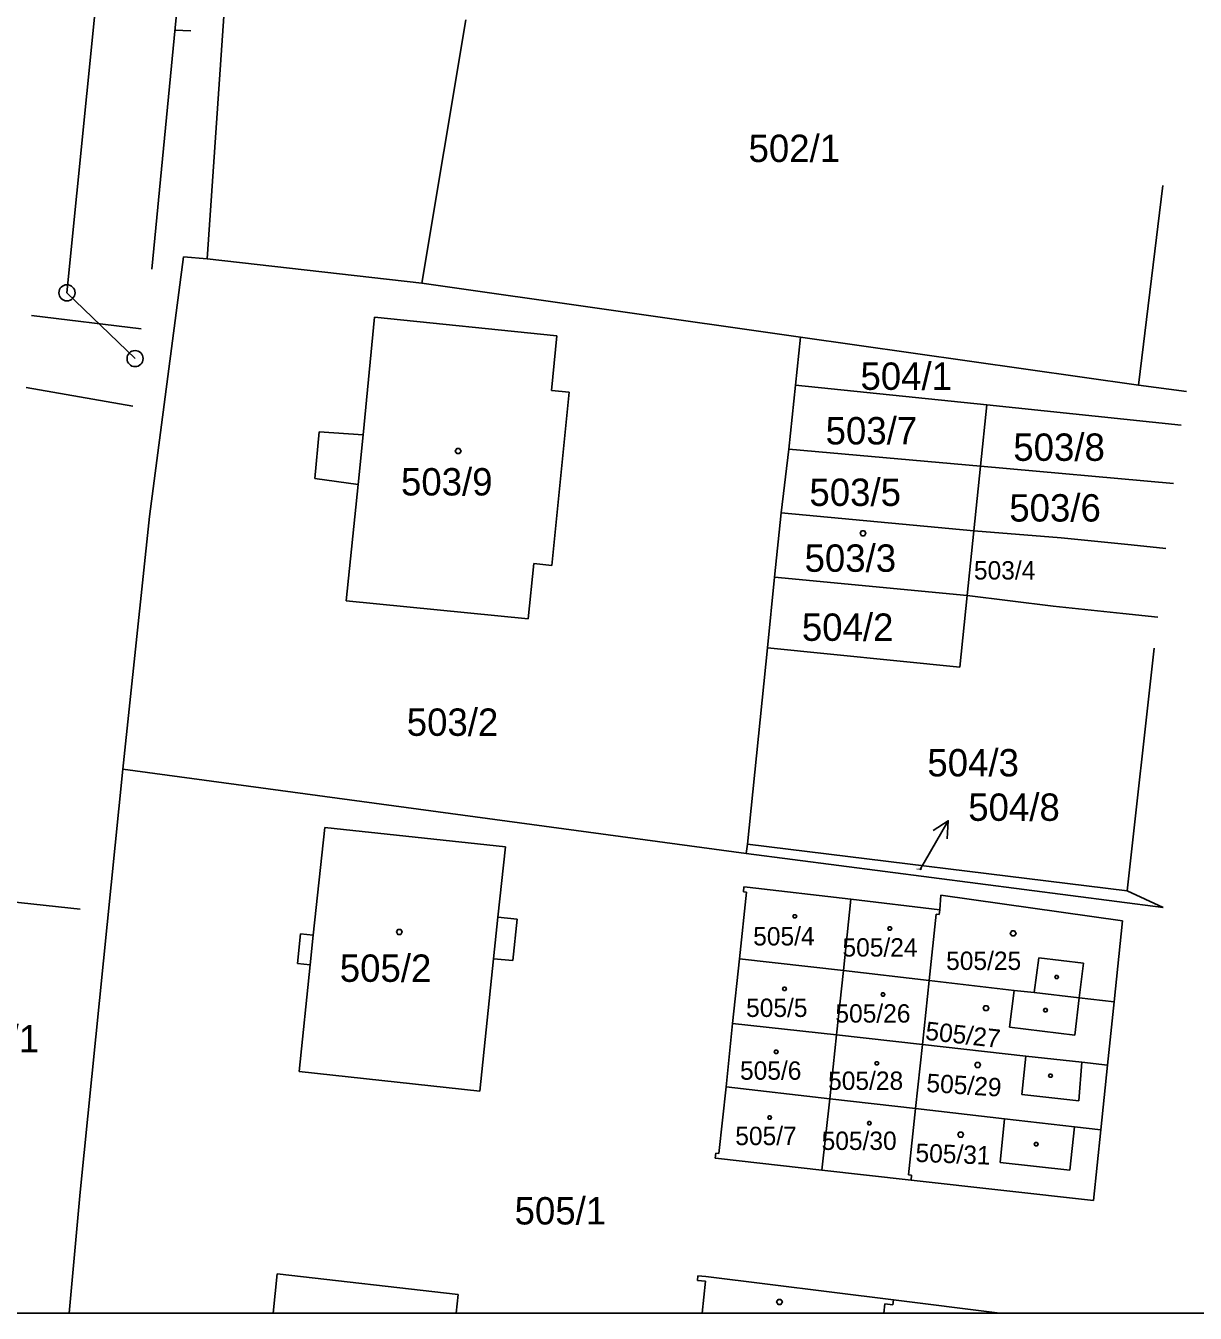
# Model space of a CAD drawing. Extents: x -639621 to -639329, y -1192893 to -1192488.
# Drawn here: x -639505.7 to -639433, y -1192893.3 to -1192813.4 of the extents above; entities that cross this region are included whole.
import ezdxf

# ---------------------------------------------------------------- set-up
doc = ezdxf.new("R2010")
doc.units = 0
for name, color, linetype in [('Vrstva 1', 7, 'Continuous'), ('Vrstva 19', 7, 'Continuous'), ('Vrstva 2', 7, 'Continuous'), ('Vrstva 24', 7, 'Continuous'), ('Vrstva 25', 7, 'Continuous'), ('Vrstva 4', 7, 'Continuous'), ('Vrstva 5', 7, 'Continuous'), ('Vrstva 61', 7, 'Continuous'), ('Vrstva 7', 7, 'Continuous')]:
    doc.layers.add(name, color=color, linetype=linetype)

msp = doc.modelspace()

# ---------------------------------------------------------------- linework, layer by layer
at = {"layer": 'Vrstva 1'}
for p, q in [((-639494.4, -1192827.84), (-639493.12, -1192809.14)), ((-639478.34, -1192813), (-639481.06, -1192829.36)), ((-639436.55, -1192835.69), (-639435.03, -1192823.29)), ((-639495.88, -1192827.71), (-639497.98, -1192843.85)), ((-639494.4, -1192827.84), (-639495.88, -1192827.71)), ((-639481.06, -1192829.36), (-639494.4, -1192827.84)), ((-639457.54, -1192832.71), (-639481.06, -1192829.36)), ((-639484.72, -1192838.77), (-639484, -1192831.47)), ((-639484, -1192831.47), (-639472.68, -1192832.62)), ((-639472.68, -1192832.62), (-639473.02, -1192836.01)), ((-639457.54, -1192832.71), (-639457.85, -1192835.68)), ((-639436.55, -1192835.69), (-639457.54, -1192832.71)), ((-639473.02, -1192836.01), (-639471.91, -1192836.12)), ((-639471.91, -1192836.12), (-639472.99, -1192846.89)), ((-639457.85, -1192835.68), (-639458.27, -1192839.66)), ((-639457.85, -1192835.68), (-639445.97, -1192836.92)), ((-639433.57, -1192836.09), (-639436.55, -1192835.69)), ((-639446.36, -1192840.72), (-639445.97, -1192836.92)), ((-639445.97, -1192836.92), (-639433.9, -1192838.17)), ((-639487.71, -1192841.49), (-639487.45, -1192838.59)), ((-639487.45, -1192838.59), (-639484.72, -1192838.77)), ((-639458.27, -1192839.66), (-639458.75, -1192843.61)), ((-639458.27, -1192839.66), (-639446.36, -1192840.72)), ((-639446.78, -1192844.73), (-639446.36, -1192840.72)), ((-639446.36, -1192840.72), (-639434.37, -1192841.8)), ((-639485.03, -1192841.85), (-639487.71, -1192841.49)), ((-639485.76, -1192849.08), (-639485.03, -1192841.85)), ((-639497.98, -1192843.85), (-639499.64, -1192859.54)), ((-639458.75, -1192843.61), (-639459.16, -1192847.61)), ((-639446.78, -1192844.73), (-639458.75, -1192843.61)), ((-639447.19, -1192848.75), (-639446.78, -1192844.73)), ((-639446.78, -1192844.73), (-639441.35, -1192845.18)), ((-639441.35, -1192845.18), (-639437.01, -1192845.61)), ((-639434.84, -1192845.83), (-639437.01, -1192845.61)), ((-639474.11, -1192846.77), (-639474.46, -1192850.2)), ((-639472.99, -1192846.89), (-639474.11, -1192846.77)), ((-639459.16, -1192847.61), (-639459.6, -1192852)), ((-639459.16, -1192847.61), (-639447.19, -1192848.75)), ((-639447.65, -1192853.2), (-639447.19, -1192848.75)), ((-639447.19, -1192848.75), (-639441.84, -1192849.41)), ((-639474.46, -1192850.2), (-639485.76, -1192849.08)), ((-639441.84, -1192849.41), (-639437.52, -1192849.88)), ((-639437.52, -1192849.88), (-639435.34, -1192850.1)), ((-639459.6, -1192852), (-639460.84, -1192864.19)), ((-639459.6, -1192852), (-639447.65, -1192853.2)), ((-639435.57, -1192852.02), (-639437.25, -1192867.1)), ((-639499.64, -1192859.54), (-639502.3, -1192885.82)), ((-639460.93, -1192864.78), (-639499.64, -1192859.54)), ((-639487.1, -1192863.17), (-639487.81, -1192869.85)), ((-639475.88, -1192864.37), (-639487.1, -1192863.17)), ((-639460.84, -1192864.19), (-639460.93, -1192864.78)), ((-639437.25, -1192867.1), (-639460.84, -1192864.19)), ((-639476.34, -1192868.73), (-639475.88, -1192864.37)), ((-639460.93, -1192864.78), (-639435.01, -1192868.14)), ((-639461.33, -1192871.31), (-639460.89, -1192867.17)), ((-639461.09, -1192867.15), (-639461.06, -1192866.85)), ((-639461.09, -1192867.15), (-639460.89, -1192867.17)), ((-639460.86, -1192866.87), (-639461.06, -1192866.85)), ((-639454.41, -1192867.62), (-639460.86, -1192866.87)), ((-639448.83, -1192867.36), (-639448.89, -1192868.27)), ((-639437.53, -1192868.96), (-639448.83, -1192867.36)), ((-639437.25, -1192867.1), (-639435.01, -1192868.14)), ((-639454.41, -1192867.62), (-639454.88, -1192872.05)), ((-639448.89, -1192868.27), (-639454.41, -1192867.62)), ((-639475.15, -1192868.85), (-639476.34, -1192868.73)), ((-639475.42, -1192871.43), (-639475.15, -1192868.85)), ((-639449.55, -1192872.67), (-639449.12, -1192868.55)), ((-639448.92, -1192868.57), (-639449.12, -1192868.55)), ((-639448.92, -1192868.57), (-639448.89, -1192868.27)), ((-639438.06, -1192873.99), (-639437.53, -1192868.96)), ((-639488.6, -1192869.77), (-639488.79, -1192871.6)), ((-639487.81, -1192869.85), (-639488.6, -1192869.77)), ((-639477.47, -1192879.53), (-639476.61, -1192871.31)), ((-639476.61, -1192871.31), (-639475.42, -1192871.43)), ((-639461.76, -1192875.34), (-639461.33, -1192871.31)), ((-639461.33, -1192871.31), (-639454.88, -1192872.05)), ((-639488.79, -1192871.6), (-639488, -1192871.69)), ((-639488, -1192871.69), (-639488.7, -1192878.32)), ((-639454.88, -1192872.05), (-639455.31, -1192876.05)), ((-639454.88, -1192872.05), (-639449.55, -1192872.67)), ((-639449.55, -1192872.67), (-639449.96, -1192876.65)), ((-639449.55, -1192872.67), (-639444.26, -1192873.28)), ((-639444.26, -1192873.28), (-639443.02, -1192873.42)), ((-639443.02, -1192873.42), (-639440.23, -1192873.74)), ((-639440.23, -1192873.74), (-639438.06, -1192873.99)), ((-639438.47, -1192877.92), (-639438.06, -1192873.99)), ((-639462.17, -1192879.28), (-639461.76, -1192875.34)), ((-639455.31, -1192876.05), (-639461.76, -1192875.34)), ((-639455.31, -1192876.05), (-639455.73, -1192880.02)), ((-639449.96, -1192876.65), (-639455.31, -1192876.05)), ((-639449.96, -1192876.65), (-639450.4, -1192880.62)), ((-639443.55, -1192877.36), (-639449.96, -1192876.65)), ((-639440.06, -1192877.74), (-639443.55, -1192877.36)), ((-639438.47, -1192877.92), (-639440.06, -1192877.74)), ((-639488.7, -1192878.32), (-639477.47, -1192879.53)), ((-639438.89, -1192881.94), (-639438.47, -1192877.92)), ((-639462.61, -1192883.42), (-639462.17, -1192879.28)), ((-639462.17, -1192879.28), (-639455.73, -1192880.02)), ((-639455.73, -1192880.02), (-639456.21, -1192884.44)), ((-639455.73, -1192880.02), (-639450.4, -1192880.62)), ((-639450.4, -1192880.62), (-639450.84, -1192884.74)), ((-639450.4, -1192880.62), (-639444.87, -1192881.26)), ((-639444.87, -1192881.26), (-639440.52, -1192881.75)), ((-639440.52, -1192881.75), (-639438.89, -1192881.94)), ((-639439.35, -1192886.33), (-639438.89, -1192881.94)), ((-639462.84, -1192883.7), (-639462.81, -1192883.4)), ((-639462.81, -1192883.4), (-639462.61, -1192883.42)), ((-639462.84, -1192883.7), (-639462.64, -1192883.72)), ((-639456.21, -1192884.44), (-639462.64, -1192883.72)), ((-639450.67, -1192885.06), (-639456.21, -1192884.44)), ((-639450.64, -1192884.76), (-639450.84, -1192884.74)), ((-639450.67, -1192885.06), (-639450.64, -1192884.76)), ((-639502.3, -1192885.82), (-639502.985, -1192893.333)), ((-639439.35, -1192886.33), (-639450.67, -1192885.06)), ((-639490.05, -1192890.89), (-639490.312, -1192893.333)), ((-639478.82, -1192892.16), (-639490.05, -1192890.89)), ((-639463.92, -1192891), (-639463.95, -1192891.3)), ((-639463.95, -1192891.3), (-639463.45, -1192891.35)), ((-639463.42, -1192891.05), (-639463.92, -1192891)), ((-639463.663, -1192893.333), (-639463.45, -1192891.35)), ((-639463.42, -1192891.05), (-639451.76, -1192892.5)), ((-639478.946, -1192893.333), (-639478.82, -1192892.16)), ((-639452.3, -1192892.75), (-639452.361, -1192893.333)), ((-639452.3, -1192892.75), (-639451.8, -1192892.81)), ((-639451.8, -1192892.81), (-639451.76, -1192892.5)), ((-639451.76, -1192892.5), (-639445.33, -1192893.31)), ((-639445.33, -1192893.31), (-639445.141, -1192893.333))]:
    msp.add_line(p, q, dxfattribs=at)
at = {"layer": 'Vrstva 19'}
msp.add_lwpolyline([(-639498.884, -1192834.039), (-639503.116, -1192829.951), (-639498.124, -1192780.201), (-639493.988, -1192740.511), (-639490.998, -1192720.223)], dxfattribs=at)
for centre in [(-639503.116, -1192829.951), (-639498.884, -1192834.039)]:
    msp.add_circle(centre, 0.5, dxfattribs=at)
at = {"layer": 'Vrstva 24'}
for p, q in [((-639497.844, -1192828.492), (-639491.5, -1192762.758)), ((-639496.412, -1192813.649), (-639495.411, -1192813.687))]:
    msp.add_line(p, q, dxfattribs=at)
at = {"layer": 'Vrstva 25'}
for p, q in [((-639505.311, -1192831.354), (-639498.513, -1192832.188)), ((-639505.652, -1192835.835), (-639499.03, -1192836.998)), ((-639508.9, -1192867.516), (-639502.289, -1192868.237))]:
    msp.add_line(p, q, dxfattribs=at)
at = {"layer": 'Vrstva 4'}
for p, q in [((-639484.72, -1192838.77), (-639485.03, -1192841.85)), ((-639476.34, -1192868.73), (-639476.61, -1192871.31)), ((-639488, -1192871.69), (-639487.81, -1192869.85)), ((-639442.74, -1192871.25), (-639443.02, -1192873.42)), ((-639439.96, -1192871.59), (-639442.74, -1192871.25)), ((-639440.23, -1192873.74), (-639439.96, -1192871.59)), ((-639444.26, -1192873.28), (-639444.55, -1192875.56)), ((-639440.51, -1192876.06), (-639440.23, -1192873.74)), ((-639444.55, -1192875.56), (-639440.51, -1192876.06)), ((-639443.55, -1192877.36), (-639443.8, -1192879.75)), ((-639440.25, -1192880.15), (-639440.06, -1192877.74)), ((-639443.8, -1192879.75), (-639440.25, -1192880.15)), ((-639444.87, -1192881.26), (-639445.13, -1192883.97)), ((-639440.82, -1192884.44), (-639440.52, -1192881.75)), ((-639445.13, -1192883.97), (-639440.82, -1192884.44)), ((-639445.33, -1192893.31), (-639445.333, -1192893.333))]:
    msp.add_line(p, q, dxfattribs=at)
at = {"layer": 'Vrstva 5'}
for points in [[(-639478.72, -1192839.63), (-639478.63, -1192839.78), (-639478.72, -1192839.93), (-639478.9, -1192839.93), (-639478.99, -1192839.78), (-639478.9, -1192839.63)], [(-639453.57, -1192844.74), (-639453.48, -1192844.89), (-639453.57, -1192845.04), (-639453.75, -1192845.04), (-639453.84, -1192844.89), (-639453.75, -1192844.74)], [(-639457.84, -1192868.58), (-639457.779, -1192868.68), (-639457.84, -1192868.78), (-639457.96, -1192868.78), (-639458.021, -1192868.68), (-639457.96, -1192868.58)], [(-639482.38, -1192869.5), (-639482.29, -1192869.65), (-639482.38, -1192869.8), (-639482.56, -1192869.8), (-639482.65, -1192869.65), (-639482.56, -1192869.5)], [(-639451.94, -1192869.34), (-639451.879, -1192869.44), (-639451.94, -1192869.54), (-639452.06, -1192869.54), (-639452.121, -1192869.44), (-639452.06, -1192869.34)], [(-639444.24, -1192869.59), (-639444.15, -1192869.74), (-639444.24, -1192869.89), (-639444.42, -1192869.89), (-639444.51, -1192869.74), (-639444.42, -1192869.59)], [(-639441.57, -1192872.35), (-639441.509, -1192872.45), (-639441.57, -1192872.55), (-639441.69, -1192872.55), (-639441.751, -1192872.45), (-639441.69, -1192872.35)], [(-639458.48, -1192873.08), (-639458.419, -1192873.18), (-639458.48, -1192873.28), (-639458.6, -1192873.28), (-639458.661, -1192873.18), (-639458.6, -1192873.08)], [(-639452.36, -1192873.43), (-639452.299, -1192873.53), (-639452.36, -1192873.63), (-639452.48, -1192873.63), (-639452.541, -1192873.53), (-639452.48, -1192873.43)], [(-639445.93, -1192874.23), (-639445.84, -1192874.38), (-639445.93, -1192874.53), (-639446.11, -1192874.53), (-639446.2, -1192874.38), (-639446.11, -1192874.23)], [(-639442.27, -1192874.41), (-639442.209, -1192874.51), (-639442.27, -1192874.61), (-639442.39, -1192874.61), (-639442.451, -1192874.51), (-639442.39, -1192874.41)], [(-639458.99, -1192876.99), (-639458.929, -1192877.09), (-639458.99, -1192877.19), (-639459.11, -1192877.19), (-639459.171, -1192877.09), (-639459.11, -1192876.99)], [(-639452.74, -1192877.71), (-639452.679, -1192877.81), (-639452.74, -1192877.91), (-639452.86, -1192877.91), (-639452.921, -1192877.81), (-639452.86, -1192877.71)], [(-639446.45, -1192877.76), (-639446.36, -1192877.91), (-639446.45, -1192878.06), (-639446.63, -1192878.06), (-639446.72, -1192877.91), (-639446.63, -1192877.76)], [(-639441.95, -1192878.48), (-639441.889, -1192878.58), (-639441.95, -1192878.68), (-639442.07, -1192878.68), (-639442.131, -1192878.58), (-639442.07, -1192878.48)], [(-639459.4, -1192881.08), (-639459.339, -1192881.18), (-639459.4, -1192881.28), (-639459.52, -1192881.28), (-639459.581, -1192881.18), (-639459.52, -1192881.08)], [(-639453.21, -1192881.43), (-639453.149, -1192881.53), (-639453.21, -1192881.63), (-639453.33, -1192881.63), (-639453.391, -1192881.53), (-639453.33, -1192881.43)], [(-639447.5, -1192882.09), (-639447.41, -1192882.24), (-639447.5, -1192882.39), (-639447.68, -1192882.39), (-639447.77, -1192882.24), (-639447.68, -1192882.09)], [(-639442.84, -1192882.73), (-639442.779, -1192882.83), (-639442.84, -1192882.93), (-639442.96, -1192882.93), (-639443.021, -1192882.83), (-639442.96, -1192882.73)], [(-639458.76, -1192892.48), (-639458.67, -1192892.63), (-639458.76, -1192892.78), (-639458.94, -1192892.78), (-639459.03, -1192892.63), (-639458.94, -1192892.48)]]:
    msp.add_lwpolyline(points, close=True, dxfattribs=at)
at = {"layer": 'Vrstva 61'}
msp.add_lwpolyline([(-639329.262, -1192893.333), (-639621.262, -1192893.333)], dxfattribs=at)
at = {"layer": 'Vrstva 7'}
for p in [(-639448.363, -1192862.746), (-639450.13, -1192865.8)]:
    msp.add_line(p, (-639449.87, -1192865.34), dxfattribs=at)
msp.add_lwpolyline([(-639449.298, -1192863.359), (-639448.363, -1192862.746), (-639448.433, -1192863.862)], dxfattribs=at)

# ---------------------------------------------------------------- texts
at = {"layer": 'Vrstva 2'}
for s, height, p in [('502/1', 1.7, (-639460.772, -1192821.83)), ('504/1', 1.7, (-639453.819, -1192835.98)), ('503/7', 1.7, (-639455.984, -1192839.37)), ('503/8', 1.7, (-639444.324, -1192840.39)), ('503/9', 1.7, (-639482.364, -1192842.54)), ('503/5', 1.7, (-639456.991, -1192843.19)), ('503/6', 1.7, (-639444.574, -1192844.16)), ('503/3', 1.7, (-639457.291, -1192847.28)), ('503/4', 1.14, (-639446.77, -1192847.76)), ('504/2', 1.7, (-639457.46, -1192851.57)), ('503/2', 1.7, (-639482.007, -1192857.47)), ('504/3', 1.7, (-639449.664, -1192859.99)), ('504/8', 0.1, (-639450.337, -1192865.8)), ('505/4', 1.14, (-639460.483, -1192870.49)), ('505/24', 1.14, (-639454.935, -1192871.18)), ('505/2', 1.7, (-639486.167, -1192872.75)), ('505/25', 1.14, (-639448.496, -1192872.01)), ('505/5', 1.14, (-639460.924, -1192874.93)), ('505/26', 1.14, (-639455.375, -1192875.28)), ('715/1', 1.7, (-639510.527, -1192877.133)), ('505/6', 1.14, (-639461.303, -1192878.83)), ('505/28', 1.14, (-639455.828, -1192879.46)), ('505/7', 1.14, (-639461.596, -1192882.89)), ('505/30', 1.14, (-639456.232, -1192883.19)), ('505/1', 1.7, (-639475.306, -1192887.82))]:
    msp.add_text(s, height=height, dxfattribs=at).set_placement(p)
for s, rotation, p in [('505/27', 353.62955, (-639449.83, -1192876.342)), ('505/29', 356.32245, (-639449.749, -1192879.584)), ('505/31', 357.81214, (-639450.418, -1192883.928))]:
    msp.add_text(s, height=1.14, rotation=rotation, dxfattribs=at).set_placement(p)
at = {"layer": 'Vrstva 7'}
msp.add_text('504/8', height=1.7, dxfattribs=at).set_placement((-639447.123, -1192862.75))

doc.saveas('drawing.dxf')
